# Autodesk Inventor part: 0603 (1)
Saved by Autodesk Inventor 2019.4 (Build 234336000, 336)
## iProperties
Created: 2021-02
Part Number: 0603 (1)
Material: Generic
Document SubType Name: Modeling
Designer: Administrator
Density: 1 g/cm^3
Appearance: Default
Title: 0603 (1)
Author: Administrator
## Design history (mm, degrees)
feature "Body1"
body "Solid1"
